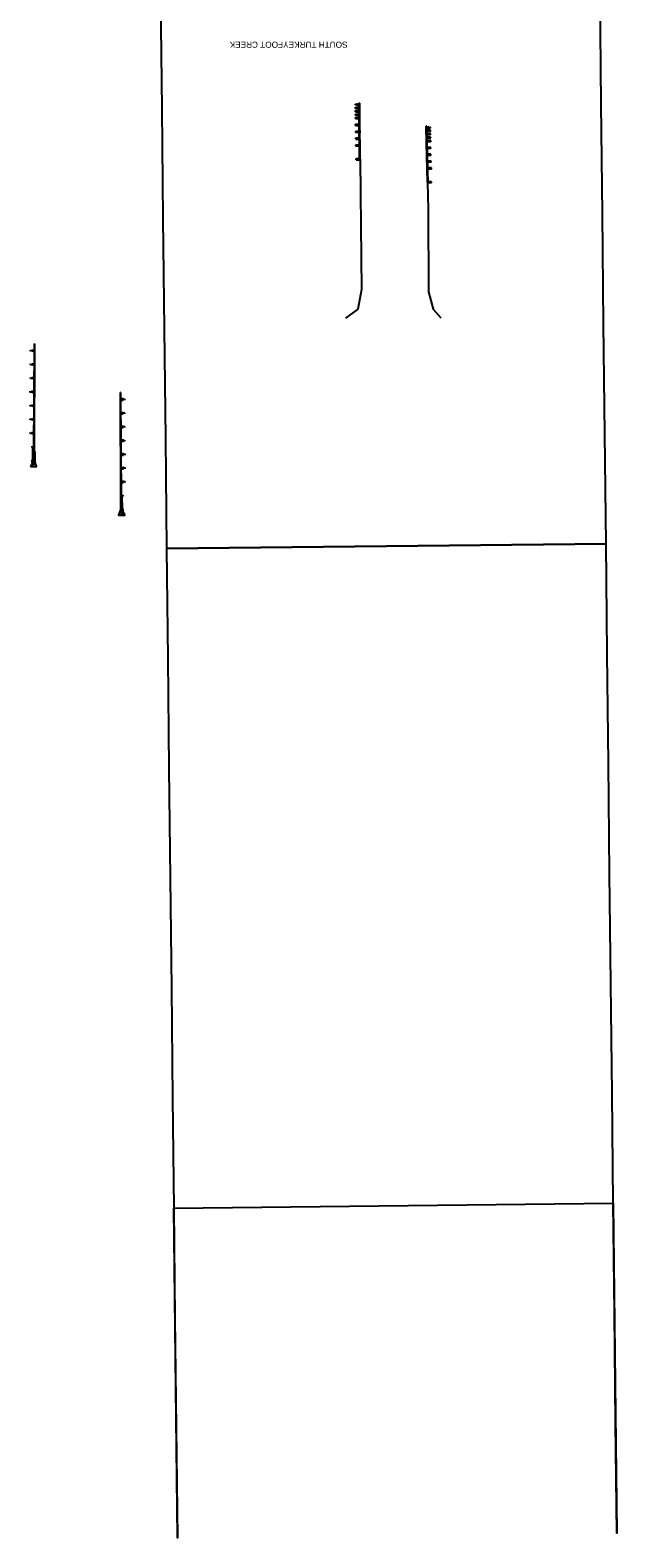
# Model space of a CAD drawing. Extents: x 181105 to 189133, y 406929 to 500404.
# Drawn here: x 181531 to 181798, y 420978 to 421664 of the extents above; entities that cross this region are included whole.
import ezdxf

# ---------------------------------------------------------------- set-up
doc = ezdxf.new("R2010")
doc.units = 0
for name, color, linetype in [('SH_Named_Boundary', 7, 'Continuous'), ('SH_Text', 7, 'Continuous'), ('SV_X_Random_Point', 7, 'Continuous'), ('UT_X_Electric_Cells', 7, 'Continuous'), ('UT_X_Telecom_Cells', 7, 'Continuous')]:
    doc.layers.add(name, color=color, linetype=linetype)

msp = doc.modelspace()

# ---------------------------------------------------------------- linework, layer by layer
at = {"layer": 'SH_Named_Boundary'}
for points in [[(181592.96, 421428.13), (181792.95, 421430.31), (181792.41, 421480.31), (181791.86, 421530.31), (181791.31, 421580.31), (181790.77, 421630.3), (181790.22, 421680.3), (181789.68, 421730.3), (181789.13, 421780.29), (181788.58, 421830.29), (181788.04, 421880.29), (181787.49, 421930.29), (181587.5, 421928.1), (181588.05, 421878.1), (181588.6, 421828.11), (181589.14, 421778.11), (181589.69, 421728.11), (181590.23, 421678.12), (181590.78, 421628.12), (181591.33, 421578.12), (181591.87, 421528.12), (181592.42, 421478.13)], [(181596.24, 421128.15), (181796.23, 421130.33), (181797.87, 420980.34), (181797.32, 421030.34), (181796.78, 421080.34), (181796.23, 421130.33), (181795.68, 421180.33), (181795.14, 421230.33), (181794.59, 421280.32), (181794.04, 421330.32), (181793.5, 421380.32), (181792.95, 421430.31), (181592.96, 421428.13), (181593.51, 421378.13), (181594.06, 421328.14), (181594.6, 421278.14), (181595.15, 421228.14), (181595.69, 421178.15), (181596.24, 421128.15), (181596.79, 421078.15), (181597.33, 421028.15), (181597.88, 420978.16)]]:
    msp.add_lwpolyline(points, close=True, dxfattribs=at)
at = {"layer": 'SV_X_Random_Point'}
msp.add_lwpolyline([(181681.11, 421605.22), (181681.28, 421589.68), (181681.74, 421545.91), (181680.05, 421537.04), (181674.34, 421532.94)], dxfattribs=at)
at = {"layer": 'UT_X_Electric_Cells'}
for p, q in [((181678.87, 421628.87), (181680.48, 421628.89)), ((181678.87, 421628.33), (181678.87, 421628.87)), ((181678.88, 421629.75), (181678.88, 421630.29)), ((181678.92, 421630.29), (181678.88, 421630.29)), ((181678.92, 421629.75), (181678.88, 421629.75)), ((181678.92, 421629.75), (181678.92, 421629.96)), ((181678.93, 421630.1), (181678.93, 421630.29)), ((181679.39, 421630.01), (181678.97, 421630)), ((181679.39, 421630.06), (181678.98, 421630.05)), ((181679.44, 421630.1), (181679.43, 421630.3)), ((181679.5, 421630.3), (181679.43, 421630.3)), ((181679.48, 421630.3), (181679.43, 421630.3)), ((181679.44, 421629.76), (181679.44, 421629.96)), ((181679.5, 421629.76), (181679.44, 421629.76)), ((181679.49, 421629.76), (181679.48, 421630.3)), ((181679.5, 421630.3), (181680.46, 421630.31)), ((181680.47, 421629.77), (181679.5, 421629.76)), ((181679.62, 421628.34), (181679.61, 421628.88)), ((181680.46, 421630.73), (181680.84, 421630.74)), ((181680.54, 421623.41), (181680.46, 421630.73)), ((181680.78, 421629.65), (181680.47, 421629.64)), ((181680.78, 421629.65), (181680.77, 421630.73)), ((181680.92, 421623.41), (181680.84, 421630.74)), ((181680.84, 421630.22), (181680.84, 421630.22)), ((181678.87, 421628.33), (181680.48, 421628.35)), ((181678.89, 421627.31), (181680.49, 421627.33)), ((181678.9, 421626.77), (181678.89, 421627.31)), ((181678.9, 421626.77), (181680.5, 421626.79)), ((181678.93, 421625.75), (181680.51, 421625.77)), ((181678.94, 421625.21), (181678.93, 421625.75)), ((181678.94, 421625.21), (181680.52, 421625.23)), ((181678.95, 421624.21), (181680.53, 421624.23)), ((181678.95, 421623.67), (181678.95, 421624.21)), ((181678.95, 421623.67), (181680.53, 421623.69)), ((181679.65, 421626.78), (181679.64, 421627.32)), ((181679.68, 421625.22), (181679.68, 421625.76)), ((181679.7, 421623.68), (181679.69, 421624.22)), ((181680.74, 421604.68), (181680.54, 421623.41)), ((181681.11, 421605.22), (181680.92, 421623.41)), ((181678.95, 421621.08), (181680.56, 421621.09)), ((181678.96, 421620.54), (181678.95, 421621.08)), ((181678.96, 421620.54), (181680.57, 421620.55)), ((181679.07, 421617.95), (181680.6, 421617.97)), ((181679.08, 421617.41), (181679.07, 421617.95)), ((181679.08, 421617.41), (181680.6, 421617.43)), ((181679.7, 421620.54), (181679.7, 421621.08)), ((181679.82, 421617.42), (181679.82, 421617.96)), ((181680.6, 421617.18), (181680.71, 421617.18)), ((181680.98, 421617.18), (181680.71, 421617.18)), ((181680.97, 421618.27), (181680.98, 421617.18)), ((181711.43, 421620.19), (181711.05, 421620.18)), ((181711.23, 421612.85), (181711.05, 421620.18)), ((181711.07, 421619.66), (181711.07, 421619.66)), ((181711.15, 421619.09), (181711.12, 421620.17)), ((181711.15, 421619.09), (181711.46, 421619.1)), ((181711.61, 421612.87), (181711.43, 421620.19)), ((181712.41, 421619.79), (181711.44, 421619.77)), ((181711.46, 421619.23), (181712.42, 421619.25)), ((181713.09, 421618.39), (181711.48, 421618.35)), ((181713.1, 421617.85), (181711.49, 421617.81)), ((181713.12, 421616.83), (181711.52, 421616.79)), ((181713.13, 421616.28), (181711.53, 421616.24)), ((181713.13, 421615.26), (181711.56, 421615.23)), ((181712.36, 421617.83), (181712.34, 421618.37)), ((181712.38, 421616.27), (181712.37, 421616.81)), ((181712.4, 421614.71), (181712.39, 421615.25)), ((181712.41, 421619.79), (181712.47, 421619.79)), ((181712.42, 421619.79), (181712.47, 421619.79)), ((181712.44, 421619.25), (181712.42, 421619.79)), ((181712.42, 421619.25), (181712.48, 421619.25)), ((181712.48, 421619.59), (181712.47, 421619.79)), ((181712.48, 421619.25), (181712.48, 421619.45)), ((181712.52, 421619.5), (181712.95, 421619.51)), ((181712.53, 421619.55), (181712.93, 421619.56)), ((181712.98, 421619.8), (181713.03, 421619.8)), ((181712.98, 421619.6), (181712.98, 421619.8)), ((181713, 421619.26), (181713, 421619.47)), ((181713.01, 421619.26), (181713.04, 421619.26)), ((181713.04, 421619.26), (181713.03, 421619.8)), ((181713.1, 421617.85), (181713.09, 421618.39)), ((181713.13, 421616.28), (181713.12, 421616.83)), ((181713.15, 421614.72), (181713.13, 421615.26)), ((181679.09, 421611.74), (181680.66, 421611.76)), ((181679.1, 421611.2), (181679.09, 421611.74)), ((181679.1, 421611.2), (181680.67, 421611.22)), ((181679.11, 421614.86), (181680.63, 421614.88)), ((181679.11, 421614.32), (181679.11, 421614.86)), ((181679.11, 421614.32), (181680.64, 421614.33)), ((181679.84, 421611.21), (181679.84, 421611.75)), ((181679.86, 421614.33), (181679.85, 421614.87)), ((181711.69, 421594.67), (181711.23, 421612.85)), ((181713.15, 421614.72), (181711.57, 421614.68)), ((181713.17, 421613.72), (181711.59, 421613.68)), ((181713.19, 421613.18), (181711.61, 421613.14)), ((181712.08, 421594.14), (181711.61, 421612.87)), ((181713.28, 421610.59), (181711.67, 421610.55)), ((181713.29, 421610.05), (181711.69, 421610.01)), ((181712.44, 421613.16), (181712.43, 421613.7)), ((181712.55, 421610.03), (181712.54, 421610.57)), ((181713.19, 421613.18), (181713.17, 421613.72)), ((181713.29, 421610.05), (181713.28, 421610.59)), ((181679.22, 421605.47), (181680.73, 421605.49)), ((181679.23, 421604.93), (181679.22, 421605.47)), ((181679.23, 421604.93), (181680.73, 421604.95)), ((181679.97, 421604.94), (181679.97, 421605.48)), ((181711.36, 421607.71), (181711.39, 421606.62)), ((181711.39, 421606.62), (181711.67, 421606.63)), ((181711.77, 421606.63), (181711.67, 421606.63)), ((181713.28, 421607.46), (181711.75, 421607.42)), ((181713.29, 421606.92), (181711.76, 421606.88)), ((181713.35, 421604.37), (181711.83, 421604.33)), ((181713.36, 421603.83), (181711.84, 421603.79)), ((181713.48, 421601.26), (181711.9, 421601.22)), ((181712.54, 421606.9), (181712.53, 421607.44)), ((181712.62, 421603.81), (181712.6, 421604.35)), ((181712.74, 421600.7), (181712.73, 421601.24)), ((181713.29, 421606.92), (181713.28, 421607.46)), ((181713.36, 421603.83), (181713.35, 421604.37)), ((181713.49, 421600.72), (181713.48, 421601.26)), ((181713.49, 421600.72), (181711.92, 421600.68)), ((181713.57, 421594.98), (181712.06, 421594.95)), ((181713.58, 421594.44), (181712.08, 421594.41)), ((181712.84, 421594.42), (181712.83, 421594.97)), ((181713.58, 421594.44), (181713.57, 421594.98)), ((181532.61, 421472.31), (181532.8, 421521.27)), ((181532.8, 421521.27), (181533.05, 421521.27)), ((181532.86, 421472.31), (181533.05, 421521.27)), ((181531.01, 421511.65), (181531.01, 421512.15)), ((181531.03, 421517.9), (181531.04, 421518.4)), ((181531.04, 421518.15), (181531.79, 421518.15)), ((181531.76, 421511.65), (181531.76, 421512.15)), ((181531.76, 421512.15), (181532.76, 421511.64)), ((181531.76, 421511.65), (181532.76, 421512.14)), ((181531.78, 421517.9), (181531.79, 421518.4)), ((181531.78, 421517.9), (181532.79, 421518.39)), ((181531.79, 421518.4), (181532.78, 421517.89)), ((181530.99, 421505.4), (181530.99, 421505.9)), ((181530.99, 421505.65), (181531.74, 421505.65)), ((181531.01, 421511.9), (181531.76, 421511.9)), ((181531.74, 421505.4), (181531.74, 421505.9)), ((181531.74, 421505.9), (181532.74, 421505.39)), ((181531.74, 421505.4), (181532.74, 421505.89)), ((181530.96, 421499.15), (181530.97, 421499.65)), ((181530.96, 421499.4), (181531.71, 421499.4)), ((181531.71, 421499.15), (181531.72, 421499.65)), ((181531.71, 421499.15), (181532.72, 421499.64)), ((181531.72, 421499.65), (181532.71, 421499.14)), ((181572.16, 421450.07), (181571.97, 421499.03)), ((181572.22, 421499.03), (181571.97, 421499.03)), ((181572.41, 421450.07), (181572.22, 421499.03)), ((181530.94, 421492.9), (181530.94, 421493.4)), ((181530.94, 421493.15), (181531.69, 421493.15)), ((181531.69, 421492.9), (181531.69, 421493.4)), ((181531.69, 421493.4), (181532.69, 421492.89)), ((181531.69, 421492.9), (181532.69, 421493.39)), ((181573.23, 421496.16), (181572.23, 421495.65)), ((181573.23, 421495.66), (181572.23, 421496.15)), ((181573.23, 421495.66), (181573.23, 421496.16)), ((181573.98, 421495.91), (181573.23, 421495.91)), ((181573.98, 421495.66), (181573.98, 421496.16)), ((181530.92, 421486.65), (181530.92, 421487.15)), ((181530.92, 421486.9), (181531.67, 421486.9)), ((181531.67, 421486.65), (181531.67, 421487.15)), ((181531.67, 421487.15), (181532.67, 421486.64)), ((181531.67, 421486.65), (181532.67, 421487.14)), ((181573.25, 421489.91), (181572.25, 421489.4)), ((181573.25, 421489.41), (181572.25, 421489.9)), ((181573.25, 421489.41), (181573.25, 421489.91)), ((181574, 421489.66), (181573.25, 421489.66)), ((181574, 421489.41), (181574, 421489.91)), ((181530.89, 421480.4), (181530.89, 421480.9)), ((181530.89, 421480.65), (181531.64, 421480.65)), ((181531.64, 421480.4), (181531.64, 421480.9)), ((181531.64, 421480.9), (181532.64, 421480.39)), ((181531.64, 421480.4), (181532.64, 421480.89)), ((181532.89, 421480.64), (181532.89, 421480.64)), ((181573.28, 421483.66), (181572.28, 421483.15)), ((181573.28, 421483.16), (181572.28, 421483.65)), ((181573.28, 421483.16), (181573.28, 421483.66)), ((181574.03, 421483.41), (181573.28, 421483.41)), ((181574.03, 421483.16), (181574.03, 421483.66)), ((181531.87, 421474.15), (181531.87, 421474.65)), ((181531.87, 421474.4), (181532.62, 421474.39)), ((181531.87, 421474.15), (181532.62, 421474.14)), ((181532.06, 421474.15), (181532.18, 421474.02)), ((181532.16, 421468.4), (181532.18, 421474.15)), ((181532.28, 421468.4), (181532.31, 421474.15)), ((181532.43, 421474.14), (181532.3, 421474.02)), ((181532.49, 421472.31), (181532.6, 421468.39)), ((181532.49, 421472.31), (181532.99, 421472.31)), ((181532.62, 421474.14), (181532.62, 421474.64)), ((181573.3, 421477.41), (181572.3, 421476.9)), ((181573.3, 421476.91), (181572.3, 421477.4)), ((181573.33, 421470.66), (181572.32, 421471.15)), ((181573.32, 421471.16), (181572.33, 421470.65)), ((181573.3, 421476.91), (181573.3, 421477.41)), ((181574.05, 421477.16), (181573.3, 421477.16)), ((181573.33, 421470.66), (181573.32, 421471.16)), ((181574.08, 421470.91), (181573.33, 421470.91)), ((181574.05, 421476.91), (181574.05, 421477.41)), ((181574.08, 421470.66), (181574.07, 421471.16)), ((181531.84, 421467.9), (181531.85, 421468.4)), ((181531.84, 421468.15), (181532.59, 421468.14)), ((181531.85, 421468.4), (181532.6, 421468.39)), ((181532.03, 421468.4), (181532.16, 421468.52)), ((181532.41, 421468.39), (181532.28, 421468.52)), ((181532.59, 421467.89), (181532.6, 421468.39)), ((181573.35, 421464.91), (181572.35, 421464.4)), ((181573.35, 421464.41), (181572.35, 421464.9)), ((181573.35, 421464.41), (181573.35, 421464.91)), ((181574.1, 421464.66), (181573.35, 421464.66)), ((181574.1, 421464.41), (181574.1, 421464.91)), ((181572.12, 421458.4), (181572.12, 421458.4)), ((181573.37, 421458.66), (181572.37, 421458.15)), ((181573.37, 421458.16), (181572.37, 421458.65)), ((181573.37, 421458.16), (181573.37, 421458.66)), ((181574.12, 421458.41), (181573.37, 421458.41)), ((181574.12, 421458.16), (181574.12, 421458.66)), ((181572.4, 421451.9), (181572.4, 421452.4)), ((181573.15, 421452.16), (181572.4, 421452.15)), ((181573.15, 421451.91), (181572.4, 421451.9)), ((181572.59, 421451.91), (181572.71, 421451.78)), ((181572.73, 421446.16), (181572.71, 421451.91)), ((181572.86, 421446.16), (181572.84, 421451.91)), ((181572.96, 421451.91), (181572.84, 421451.78)), ((181573.15, 421451.91), (181573.15, 421452.41)), ((181572.53, 421450.07), (181572.03, 421450.07)), ((181572.53, 421450.07), (181572.42, 421446.15)), ((181573.17, 421446.16), (181572.42, 421446.15)), ((181572.42, 421445.65), (181572.42, 421446.15)), ((181573.17, 421445.91), (181572.42, 421445.9)), ((181572.61, 421446.16), (181572.73, 421446.28)), ((181572.98, 421446.16), (181572.86, 421446.28)), ((181573.17, 421445.66), (181573.17, 421446.16))]:
    msp.add_line(p, q, dxfattribs=at)
for points in [[(181531.76, 421511.65), (181531.76, 421512.15), (181532.76, 421512.14), (181532.76, 421511.64)], [(181531.78, 421517.9), (181531.79, 421518.4), (181532.79, 421518.39), (181532.78, 421517.89)], [(181531.74, 421505.4), (181531.74, 421505.9), (181532.74, 421505.89), (181532.74, 421505.39)], [(181531.71, 421499.15), (181531.72, 421499.65), (181532.72, 421499.64), (181532.71, 421499.14)], [(181531.69, 421492.9), (181531.69, 421493.4), (181532.69, 421493.39), (181532.69, 421492.89)], [(181573.23, 421495.66), (181573.23, 421496.16), (181572.23, 421496.15), (181572.23, 421495.65)], [(181531.67, 421486.65), (181531.67, 421487.15), (181532.67, 421487.14), (181532.67, 421486.64)], [(181573.25, 421489.41), (181573.25, 421489.91), (181572.25, 421489.9), (181572.25, 421489.4)], [(181531.64, 421480.4), (181531.64, 421480.9), (181532.64, 421480.89), (181532.64, 421480.39)], [(181573.28, 421483.16), (181573.28, 421483.66), (181572.28, 421483.65), (181572.28, 421483.15)], [(181573.3, 421476.91), (181573.3, 421477.41), (181572.3, 421477.4), (181572.3, 421476.9)], [(181573.33, 421470.66), (181573.32, 421471.16), (181572.32, 421471.15), (181572.33, 421470.65)], [(181533.71, 421465.51), (181532.97, 421467.64), (181532.22, 421467.65), (181531.21, 421465.77), (181531.21, 421465.4), (181533.71, 421465.39)], [(181532.59, 421467.64), (181532.59, 421467.48), (181531.84, 421467.48), (181531.84, 421467.65)], [(181573.35, 421464.41), (181573.35, 421464.91), (181572.35, 421464.9), (181572.35, 421464.4)], [(181573.37, 421458.16), (181573.37, 421458.66), (181572.37, 421458.65), (181572.37, 421458.15)], [(181571.31, 421443.28), (181572.05, 421445.4), (181572.8, 421445.41), (181573.8, 421443.53), (181573.81, 421443.16), (181571.31, 421443.15)], [(181572.42, 421445.4), (181572.42, 421445.24), (181573.17, 421445.24), (181573.17, 421445.41)]]:
    msp.add_lwpolyline(points, close=True, dxfattribs=at)
for points in [[(181532.99, 421472.31), (181532.97, 421467.64), (181532.59, 421467.64), (181532.6, 421468.39)], [(181531.21, 421465.4), (181531.21, 421465.52), (181533.71, 421465.51)], [(181572.03, 421450.07), (181572.05, 421445.4), (181572.42, 421445.4), (181572.42, 421446.15)], [(181573.81, 421443.16), (181573.81, 421443.28), (181571.31, 421443.28)]]:
    msp.add_lwpolyline(points, dxfattribs=at)
for centre, start, end in [((181531.09, 421467.65), 273.76144, 359.78251), ((181573.93, 421445.41), 180.21749, 266.23856)]:
    msp.add_arc(centre, 1.88, start, end, dxfattribs=at)
for centre, major_axis, start_param, end_param in [((181678.97, 421629.96), (-0.0497, -0.0005), 4.712389, 6.283185), ((181678.98, 421630.1), (-0.0497, -0.0005), 0, 1.570796), ((181679.39, 421630.1), (0.0497, 0.0005), 4.712389, 6.283185), ((181679.39, 421629.96), (-0.0497, -0.0005), 3.141593, 4.712389), ((181712.53, 421619.45), (0.0497, 0.0012), 1.570796, 3.141593), ((181712.53, 421619.59), (-0.0497, -0.0012), 0, 1.570796), ((181712.93, 421619.6), (0.0497, 0.0012), 4.712389, 6.283185), ((181712.95, 421619.47), (0.0497, 0.0012), 0, 1.570796)]:
    msp.add_ellipse(centre, major_axis=major_axis, ratio=0.906762, start_param=start_param, end_param=end_param, dxfattribs=at)
at = {"layer": 'UT_X_Telecom_Cells'}
msp.add_lwpolyline([(181711.69, 421594.67), (181711.99, 421582.48), (181712.18, 421544.86), (181714.23, 421537.04), (181717.76, 421533.09)], dxfattribs=at)

# ---------------------------------------------------------------- texts
at = {"layer": 'SH_Text'}
msp.add_text('SOUTH TURKEYFOOT CREEK', height=2.8, rotation=180, dxfattribs=at).set_placement((181675.32, 421658.68))

doc.saveas('drawing.dxf')
